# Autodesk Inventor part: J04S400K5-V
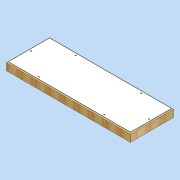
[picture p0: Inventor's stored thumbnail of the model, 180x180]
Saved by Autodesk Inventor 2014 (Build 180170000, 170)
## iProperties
Created: 2011-04
Part Number: J04S400K5-V
Document SubType Name: Modeling
Designer: david.appleford
Density: 0.438475 g/cm^3
Description: Joist 1w x 400mm - Locks 5
Mass: 16000 g
Surface Area: 11708.8 cm^2
Volume: 36490.1 cm^3
Cost Center: £60.00
Material: 000 Redwood
Appearance: Wood (Pine)
Justset: False
Title: Joist 1w x 400mm - Locks 5
Author: david.appleford
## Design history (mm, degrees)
sketch "Sketch1"
  geometry: L1 (0, 0)-(1220, 0); L2 (1220, 0)-(1220, 468); L3 (1220, 468)-(0, 468); L4 (0, 468)-(0, 0); L5 (34, 434)-(1186, 434); L6 (1186, 434)-(1186, 34); L7 (1186, 34)-(34, 34); L8 (34, 34)-(34, 434)
  constraints: 16 end point, 4 parallel, 2 perpendicular, 1 horizontal, 3 other
  dimensions: "d0" = 1220 distance between parallel lines of L2 L4 (= w); "d1" = 468 distance between parallel lines of L1 L3; "d2" = 34 distance between parallel lines of L5 L3 (= 0.5 x t); "d30" = 400 distance between parallel lines of L7 L5 (derived); "d31" = 1152 distance between parallel lines of L6 L8 (derived)
extrude "Extrusion1" new body sketch "Sketch1" distance "d3" = 68 (= t); taper "d4" = 0 deg
sketch "Sketch2"
  geometry: L1 (1186, 434)-(1186, 34) reference; L2 (34, 434)-(1186, 434) reference; L3 (34, 34)-(34, 434) reference; L4 (1186, 34)-(34, 34) reference; L5 (1176, 424)-(1176, 44); L6 (1176, 44)-(44, 44); L7 (44, 44)-(44, 424); L8 (44, 424)-(1176, 424); 1 further point
  constraints: 8 end point, 3 other
  dimensions: "d5" = 10 distance between parallel lines of L8 L2
extrude "Extrusion2" join sketch "Sketch2" distance "d6" = 6 (= sw); taper "d7" = 0 deg
sketch "Sketch3"
  geometry: L1 (-44, 424)-(-1176, 424) reference; L2 (-1176, 424)-(-1176, 44) reference; L3 (-44, 44)-(-44, 424) reference; L4 (-1176, 44)-(-44, 44) reference; 1 further point
extrude "Extrusion3" join sketch "Sketch3" distance "d8" = 6 (= sw); taper "d9" = 0 deg
sketch "Sketch4"
  geometry: L1 (34, 434)-(1186, 434) reference; L2 (1186, 434)-(1186, 34) reference; L3 (1186, 34)-(34, 34) reference; L4 (34, 34)-(34, 434) reference; 7 further points
  constraints: 3 horizontal alignment, 2 vertical alignment
  dimensions: "d10" = 28 distance from line of point (305, 406) L1 (= k); "d12" = 28 distance from line of L3 point (915, 62) (= k); "d13" = 28 distance from line of point (62, 234) L4 (= k); "d14" = 305 horizontal distance of point (305, 406) point (0, 0) (= 0.25 x w); "d15" = 610 horizontal distance of point (915, 62) point (305, 406) (= 0.5 x w); "d29" = 28 distance from line of L2 point (1158, 234) (= d13); "d32" = 400 distance between parallel lines of L3 L1 (derived); "d33" = 200 distance from line of L1 point (62, 234) (= 0.5 x d32)
hole "Hole1" sketch "Sketch4" at (305, 406), (62, 234), (915, 62), (1158, 234), (915, 406), (305, 62) diameter "d22" = 12 (= hd); stored, may be unused: countersink angle "d26" = 90 deg, drill point angle "d28" = 118 deg; dims "d23" = 6, "d24" = 4, "d25" = 2, "d27" = 8
body "Solid1"
node "Projected Loop1"
other parameters: "w" = 1220 [user parameter; used in 3 equation terms], "t" = 68 [user parameter; used in 2 equation terms], "e" = 16 [user parameter], "sw" = 6 [user parameter; used in 2 equation terms], "sc" = 9 [user parameter], "sf" = 12 [user parameter], "k" = 28 [user parameter; used in 3 equation terms], "hd" = 12 [user parameter; used in 1 equation term]
